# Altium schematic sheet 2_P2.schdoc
size 307 x 218 mm; Symbol: Sheet-Symbol_A4; Device: Sheet-Symbol_A4; @Project Name: Hexapod; @Page Count: 4; @Update Date: 2024-12-11; @Create Date: 2024-11-23; @Schematic Name: Schematic; @Page No: 2; @Page Name: P2; Company: EasyEDA.com; Version: V1.0; Page Size: A4; @Create Time: 16:43:26; @Update Time: 19:51:16; Title Block Position: 3; Width: 1170; Height: 825; Region Start: 1; X Region Count: 6; Y Region Count: 4; Blade Width: 10; @Board Name: PENTASLAM
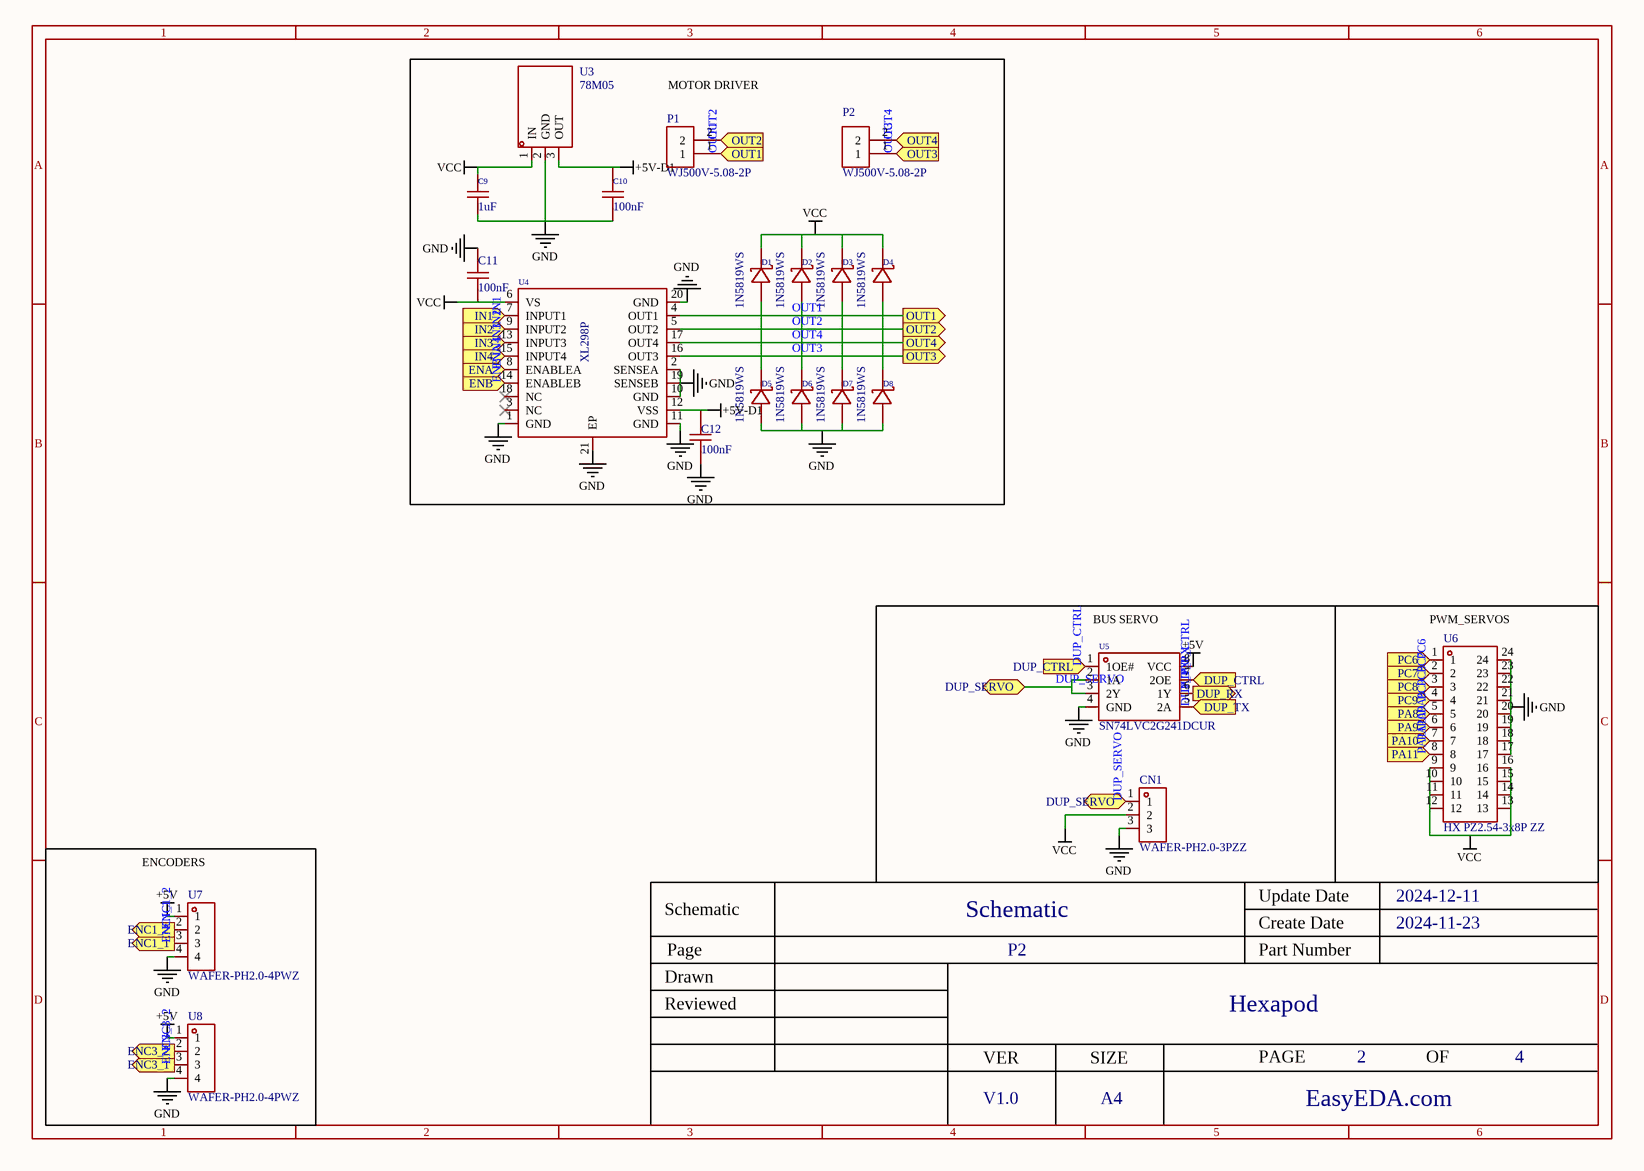
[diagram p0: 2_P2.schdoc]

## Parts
C9  1uF  [C0402]
C10  100nF  [C0402]
C11  100nF  [C0402]
C12  100nF  [C0402]
CN1  WAFER-PH2.0-3PZZ  [CONN-TH_PH2.0D-L-3P]
D1  1N5819WS  [SOD-323_L1.8-W1.3-LS2.5-RD]
D2  1N5819WS  [SOD-323_L1.8-W1.3-LS2.5-RD]
D3  1N5819WS  [SOD-323_L1.8-W1.3-LS2.5-RD]
D4  1N5819WS  [SOD-323_L1.8-W1.3-LS2.5-RD]
D5  1N5819WS  [SOD-323_L1.8-W1.3-LS2.5-RD]
D6  1N5819WS  [SOD-323_L1.8-W1.3-LS2.5-RD]
D7  1N5819WS  [SOD-323_L1.8-W1.3-LS2.5-RD]
D8  1N5819WS  [SOD-323_L1.8-W1.3-LS2.5-RD]
P1  WJ500V-5.08-2P  [CONN-TH_2P-P5.00_WJ500V-5.08-2P]
P2  WJ500V-5.08-2P  [CONN-TH_2P-P5.00_WJ500V-5.08-2P]
U3  78M05  [TO-252-2_L6.6-W6.1-P4.57-LS9.9-BR-CW]
U4  XL298P  [HSOP-20_L15.9-W11.0-P1.27-LS14.2-BL-EP]
U5  SN74LVC2G241DCUR  [VSSOP-8_L2.3-W2.0-P0.50-LS3.1-BR]
U6  HX PZ2.54-3x8P ZZ  [HDR-TH_24P-P2.54-V-F-R3-C8-S2.54]
U7  WAFER-PH2.0-4PWZ  [CONN-TH_4P-P2.00_WAFER-HY2.0-4PWZ]
U8  WAFER-PH2.0-4PWZ  [CONN-TH_4P-P2.00_WAFER-HY2.0-4PWZ]

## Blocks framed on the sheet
MOTOR DRIVER: C9-C12 D1-D8 P1 P2 U3 U4
BUS SERVO: CN1 U5
PWM_SERVOS: U6
ENCODERS: U7 U8

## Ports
DUP_CTRL (in), DUP_RX (out), DUP_SERVO (bidir), DUP_TX (in), ENA (in), ENB (in), ENC1_1 (out), ENC1_2 (out), ENC3_1 (out), ENC3_2 (out), IN1 (in), IN2 (in), IN3 (in), IN4 (in), OUT1 (in), OUT1 (out), OUT2 (in), OUT2 (out), OUT3 (in), OUT3 (out), OUT4 (in), OUT4 (out), PA8 (in), PA9 (in), PA10 (in), PA11 (in), PC6 (in), PC7 (in), PC8 (in), PC9 (in)

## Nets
+5V: U5.8(VCC) U7.1 U8.1
+5V-D1: C10.2 C12.2 U3.3(OUT) U4.12(VSS)
GND: C9.1 C10.1 C11.1 C12.1 CN1.3 D5.2(A) D6.2(A) D7.2(A) D8.2(A) U3.2(GND) U4.1(GND) U4.2(SENSEA) U4.10(GND) U4.11(GND) U4.19(SENSEB) U4.20(GND) U4.21(EP) U5.4(GND) U6.17 U6.18 U6.19 U6.20 U6.21 U6.22 U6.23 U6.24 U7.4 U8.4
VCC: C9.2 C11.2 CN1.2 D1.1(K) D2.1(K) D3.1(K) D4.1(K) U3.1(IN) U4.6(VS) U6.9 U6.10 U6.11 U6.12 U6.13 U6.14 U6.15 U6.16
DUP_CTRL: U5.1(1OE#) U5.7(2OE) ; port DUP_CTRL
DUP_RX: U5.6(1Y) ; port DUP_RX
DUP_SERVO: CN1.1 U5.2(1A) U5.3(2Y) ; port DUP_SERVO
DUP_TX: U5.5(2A) ; port DUP_TX
ENA: U4.8(ENABLEA) ; port ENA
ENB: U4.14(ENABLEB) ; port ENB
ENC1_1: U7.3 ; port ENC1_1
ENC1_2: U7.2 ; port ENC1_2
ENC3_1: U8.3 ; port ENC3_1
ENC3_2: U8.2 ; port ENC3_2
IN1: U4.7(INPUT1) ; port IN1
IN2: U4.9(INPUT2) ; port IN2
IN3: U4.13(INPUT3) ; port IN3
IN4: U4.15(INPUT4) ; port IN4
OUT1: D1.2(A) D5.1(K) P1.1 U4.4(OUT1) ; port OUT1
OUT2: D2.2(A) D6.1(K) P1.2 U4.5(OUT2) ; port OUT2
OUT3: D4.2(A) D8.1(K) P2.1 U4.16(OUT3) ; port OUT3
OUT4: D3.2(A) D7.1(K) P2.2 U4.17(OUT4) ; port OUT4
PA8: U6.5 ; port PA8
PA9: U6.6 ; port PA9
PA10: U6.7 ; port PA10
PA11: U6.8 ; port PA11
PC6: U6.1 ; port PC6
PC7: U6.2 ; port PC7
PC8: U6.3 ; port PC8
PC9: U6.4 ; port PC9

Not connected (* = marked no-connect by the designer): U4 3(NC)* 18(NC)*

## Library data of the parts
C9 = CL05A105KP5NNNC: Manufacturer: SAMSUNG(三星); Add into BOM: yes; Tolerance: ±10%
C10 = CT41G-0402-2X1-16V-0.1μF-K(N): Manufacturer: TORCH(火炬); Add into BOM: yes; Tolerance: ±10%
C11 C12 = GRM155R71C104KA88D: Manufacturer: muRata(村田); Add into BOM: yes; Tolerance: ±10%
CN1 = WAFER-PH2.0-3PZZ: Manufacturer: XUNPU(讯普); Add into BOM: yes; Pins Structure: 1x3P; Pitch: 2mm; Reference Series: PH; Number of PINs Per Row: 3; Current Rating (Max): 2A
D1-D8 = 1N5819WS_C191023: Manufacturer: Hottech(合科泰); Add into BOM: yes; Forward Voltage (Vf@If): 600mV@1A; Reverse Voltage (Vr): 40V; Average Rectified Current (Io): 1A
P1 P2 = WJ500V-5.08-2P: Manufacturer: KANGNEX(康奈克斯电气); Symbol: WJ500V-5.08-2P-14-00A; Add into BOM: yes; Structure: 1x2P; Pitch: 5.08mm; Current Rating (Max): 18A; Voltage Rating (Max): 250V; Wire Gauge - AWG: 14~30; Wire Gauge - mm2: 2.5; Number of PINs Per Row: 2; Screw Specification: M2.5
U3 = 78M05_C347278: Manufacturer: UMW(友台半导体); Symbol: UMW78M05; Add into BOM: yes; Output Type: Fixed; Maximum Input Voltage: 35V; Output Voltage: 5V; Output Current: 1A; Power Supply Rejection Ratio (PSRR): 80dB@(120Hz); Dropout Voltage: 2V@(500mA); standby current: 6mA; Output Polarity: Positive electrode; Number of Outputs: 1
U4 = XL298P: Manufacturer: XINLUDA(信路达); Add into BOM: yes
U5 = SN74LVC2G241DCUR: Manufacturer: TI(德州仪器); Add into BOM: yes
U6 = HX PZ2.54-3x8P ZZ: Manufacturer: hanxia(韩下); Add into BOM: yes; Pin Structure: 3x8P; Pitch: 2.54mm; Circluar Pins/Square Pins: Policy; Current Rating (Max): 3A
U7 U8 = WAFER-PH2.0-4PWZ: Manufacturer: XUNPU(讯普); Add into BOM: yes; Pins Structure: 1x4P; Pitch: 2mm; Reference Series: PH; Number of PINs Per Row: 4; Current Rating (Max): 2A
